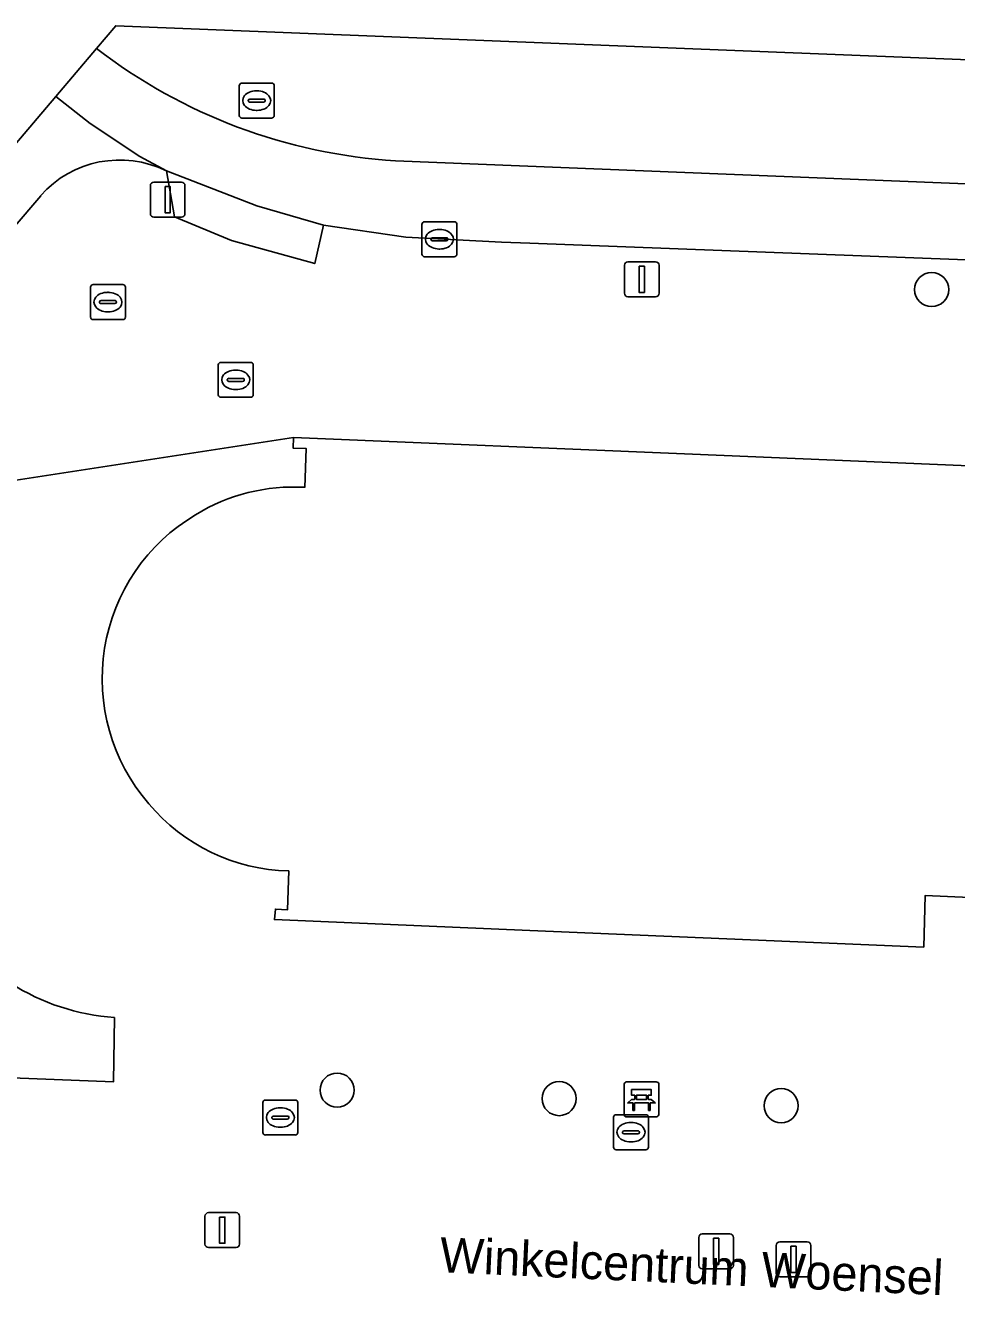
# Model space of a CAD drawing. Extents: x 160888 to 161385, y 386490 to 386908.
# Drawn here: x 160985.57 to 161012.2, y 386871.04 to 386907.8 of the extents above; entities that cross this region are included whole.
import ezdxf

# ---------------------------------------------------------------- set-up
doc = ezdxf.new("R2010")
doc.units = 0
for name, color, linetype in [('IMGEO_Bank', 7, 'Continuous'), ('IMGEO_Boom', 7, 'Continuous'), ('IMGEO_Brandkraan', 7, 'Continuous'), ('IMGEO_Fietspad_open', 7, 'Continuous'), ('IMGEO_Groenvoorziening', 7, 'Continuous'), ('IMGEO_Kolk', 7, 'Continuous'), ('IMGEO_Lichtmast', 7, 'Continuous'), ('IMGEO_Openbare_ruimte_label', 7, 'Continuous'), ('IMGEO_Pand', 7, 'Continuous'), ('IMGEO_Rijbaan_lokaal_gesloten', 7, 'Continuous'), ('IMGEO_Rioolput', 7, 'Continuous'), ('IMGEO_Voetpad_open', 7, 'Continuous')]:
    doc.layers.add(name, color=color, linetype=linetype)

msp = doc.modelspace()

# ---------------------------------------------------------------- linework, layer by layer
at = {"layer": 'IMGEO_Bank'}
for p, q in [((161002.695, 386876.655), (161002.695, 386877.496)), ((161002.695, 386877.496), (161002.695, 386876.655)), ((161002.77, 386877.58), (161003.611, 386877.58)), ((161003.611, 386877.58), (161002.77, 386877.58)), ((161003.695, 386877.505), (161003.695, 386876.664)), ((161003.695, 386876.664), (161003.695, 386877.505)), ((161003.004, 386877.086), (161003.004, 386877.192)), ((161003.048, 386877.192), (161003.048, 386877.086)), ((161003.336, 386877.198), (161003.054, 386877.198)), ((161003.054, 386877.08), (161003.336, 386877.08)), ((161003.342, 386877.086), (161003.342, 386877.192)), ((161003.386, 386877.192), (161003.386, 386877.086)), ((161003.392, 386876.978), (161002.999, 386876.978)), ((161003.62, 386876.58), (161002.779, 386876.58)), ((161002.779, 386876.58), (161003.62, 386876.58))]:
    msp.add_line(p, q, dxfattribs=at)
for points in [[(161002.942, 386876.978), (161002.8, 386876.978), (161002.912, 386877.08), (161002.998, 386877.08)], [(161002.998, 386877.198), (161002.912, 386877.198), (161002.912, 386877.359), (161003.475, 386877.359), (161003.475, 386877.198), (161003.392, 386877.198)], [(161003.392, 386877.08), (161003.475, 386877.08), (161003.587, 386876.978), (161003.448, 386876.978)], [(161002.992, 386876.971), (161002.992, 386876.764), (161002.949, 386876.764), (161002.949, 386876.971)], [(161003.442, 386876.971), (161003.442, 386876.764), (161003.398, 386876.764), (161003.398, 386876.971)]]:
    msp.add_lwpolyline(points, dxfattribs=at)
for centre, radius, start, end in [((161002.773, 386877.502), 0.0779, 92.4484, 184.2845), ((161002.773, 386877.502), 0.0779, 92.4484, 184.2845), ((161003.617, 386877.502), 0.0779, 2.4484, 94.2845), ((161003.617, 386877.502), 0.0779, 2.4484, 94.2845), ((161002.997, 386877.191), 0.00671, 2.8957, 87.1043), ((161002.997, 386877.087), 0.00671, 272.8957, 357.1043), ((161003.054, 386877.191), 0.00671, 92.8957, 177.1043), ((161003.054, 386877.087), 0.00671, 182.8957, 267.1043), ((161003.336, 386877.191), 0.00671, 2.8957, 87.1043), ((161003.336, 386877.087), 0.00671, 272.8957, 357.1043), ((161003.393, 386877.191), 0.00671, 92.8957, 177.1043), ((161003.393, 386877.087), 0.00671, 182.8957, 267.1043), ((161002.942, 386876.971), 0.00671, 2.8957, 87.1043), ((161002.999, 386876.971), 0.00671, 92.8957, 177.1043), ((161003.391, 386876.971), 0.00671, 2.8957, 87.1043), ((161003.448, 386876.971), 0.00671, 92.8957, 177.1043), ((161002.773, 386876.658), 0.0779, 182.4484, 274.2845), ((161002.773, 386876.658), 0.0779, 182.4484, 274.2845), ((161003.617, 386876.658), 0.0779, 272.4484, 4.2845), ((161003.617, 386876.658), 0.0779, 272.4484, 4.2845)]:
    msp.add_arc(centre, radius, start, end, dxfattribs=at)
at = {"layer": 'IMGEO_Boom'}
for centre in [(161011.496, 386900.25), (160994.484, 386877.344), (161000.837, 386877.102), (161007.19, 386876.899)]:
    msp.add_circle(centre, 0.489, dxfattribs=at)
at = {"layer": 'IMGEO_Brandkraan'}
for p, q in [((160987.426, 386899.465), (160987.426, 386900.317)), ((160987.501, 386900.391), (160988.353, 386900.391)), ((160988.427, 386900.317), (160988.427, 386899.465)), ((160987.685, 386899.885), (160987.685, 386899.897)), ((160987.728, 386899.934), (160988.126, 386899.934)), ((160987.914, 386900.171), (160987.939, 386900.171)), ((160988.169, 386899.897), (160988.169, 386899.885)), ((160988.123, 386899.848), (160987.725, 386899.848)), ((160987.937, 386899.611), (160987.912, 386899.611)), ((160988.353, 386899.391), (160987.501, 386899.391))]:
    msp.add_line(p, q, dxfattribs=at)
for points in [[(160987.426, 386899.465), (160987.426, 386900.317)], [(160987.501, 386900.391), (160988.353, 386900.391)], [(160988.427, 386900.317), (160988.427, 386899.465)], [(160988.353, 386899.391), (160987.501, 386899.391)]]:
    msp.add_lwpolyline(points, dxfattribs=at)
for centre, radius, start, end in [((160987.503, 386900.315), 0.0765, 91.552, 178.448), ((160987.503, 386900.315), 0.0765, 91.552, 178.448), ((160988.351, 386900.315), 0.0765, 1.552, 88.448), ((160988.351, 386900.315), 0.0765, 1.552, 88.448), ((160987.725, 386899.894), 0.0403, 85.8775, 175.7526), ((160987.722, 386899.884), 0.0366, 178.938, 274.7102), ((160988.126, 386899.891), 0.043, 264.8664, 352.4533), ((160988.13, 386899.896), 0.0386, 1.7309, 96.639), ((160987.503, 386899.467), 0.0765, 181.552, 268.448), ((160987.503, 386899.467), 0.0765, 181.552, 268.448), ((160988.351, 386899.467), 0.0765, 271.552, 358.448), ((160988.351, 386899.467), 0.0765, 271.552, 358.448)]:
    msp.add_arc(centre, radius, start, end, dxfattribs=at)
for centre, major_axis, ratio, start_param, end_param in [((160987.913, 386899.891), (-0.387, 0.002), 0.722429, 4.712389, 7.853982), ((160987.938, 386899.891), (-0.39, 0.002), 0.717154, 1.570796, 4.712389)]:
    msp.add_ellipse(centre, major_axis=major_axis, ratio=ratio, start_param=start_param, end_param=end_param, dxfattribs=at)
at = {"layer": 'IMGEO_Fietspad_open'}
for points in [[(160989.598, 386903.645), (160988.842, 386904.061), (160987.414, 386904.997), (160986.431, 386905.776), (160986.431, 386905.776), (160961.742, 386876.676), (160958.056, 386876.81)], [(160964.887, 386878.266), (160981.133, 386897.248), (160986.001, 386902.936)]]:
    msp.add_lwpolyline(points, dxfattribs=at)
msp.add_arc((160988.262, 386900.942), 3.015, 63.7043, 138.5969, dxfattribs=at)
at = {"layer": 'IMGEO_Groenvoorziening'}
msp.add_lwpolyline([(160984.295, 386894.643), (160982.853, 386895.847), (160973.768, 386885.289), (160973.52, 386878.149), (160988.085, 386877.583), (160988.113, 386879.42)], dxfattribs=at)
msp.add_arc((160988.551, 386885.739), 6.334, 237.4467, 266.031, dxfattribs=at)
at = {"layer": 'IMGEO_Kolk'}
for p, q in [((160996.911, 386901.264), (160996.911, 386902.116)), ((160996.986, 386902.19), (160997.838, 386902.19)), ((160997.912, 386902.116), (160997.912, 386901.264)), ((160997.17, 386901.684), (160997.17, 386901.696)), ((160997.213, 386901.733), (160997.611, 386901.733)), ((160997.399, 386901.97), (160997.424, 386901.97)), ((160997.654, 386901.696), (160997.654, 386901.684)), ((160997.608, 386901.647), (160997.21, 386901.647)), ((160997.422, 386901.41), (160997.397, 386901.41)), ((160997.838, 386901.19), (160996.986, 386901.19)), ((160992.359, 386876.134), (160992.359, 386876.986)), ((160992.434, 386877.06), (160993.286, 386877.06)), ((160992.847, 386876.84), (160992.872, 386876.84)), ((160993.36, 386876.986), (160993.36, 386876.134)), ((160992.618, 386876.554), (160992.618, 386876.566)), ((160993.056, 386876.517), (160992.658, 386876.517)), ((160992.661, 386876.603), (160993.059, 386876.603)), ((160993.102, 386876.566), (160993.102, 386876.554)), ((161002.393, 386875.714), (161002.393, 386876.566)), ((161002.468, 386876.64), (161003.32, 386876.64)), ((161002.881, 386876.42), (161002.906, 386876.42)), ((161003.394, 386876.566), (161003.394, 386875.714)), ((160993.286, 386876.06), (160992.434, 386876.06)), ((160992.87, 386876.28), (160992.845, 386876.28)), ((161002.652, 386876.134), (161002.652, 386876.146)), ((161003.09, 386876.097), (161002.692, 386876.097)), ((161002.695, 386876.183), (161003.093, 386876.183)), ((161003.136, 386876.146), (161003.136, 386876.134)), ((161003.32, 386875.64), (161002.468, 386875.64)), ((161002.904, 386875.86), (161002.879, 386875.86))]:
    msp.add_line(p, q, dxfattribs=at)
for points in [[(160996.911, 386901.264), (160996.911, 386902.116)], [(160996.986, 386902.19), (160997.838, 386902.19)], [(160997.912, 386902.116), (160997.912, 386901.264)], [(160997.838, 386901.19), (160996.986, 386901.19)], [(160992.359, 386876.134), (160992.359, 386876.986)], [(160992.434, 386877.06), (160993.286, 386877.06)], [(160993.36, 386876.986), (160993.36, 386876.134)], [(161002.393, 386875.714), (161002.393, 386876.566)], [(161002.468, 386876.64), (161003.32, 386876.64)], [(161003.394, 386876.566), (161003.394, 386875.714)], [(160993.286, 386876.06), (160992.434, 386876.06)], [(161003.32, 386875.64), (161002.468, 386875.64)]]:
    msp.add_lwpolyline(points, dxfattribs=at)
for centre, radius, start, end in [((160996.988, 386902.114), 0.0765, 91.552, 178.448), ((160996.988, 386902.114), 0.0765, 91.552, 178.448), ((160997.836, 386902.114), 0.0765, 1.552, 88.448), ((160997.836, 386902.114), 0.0765, 1.552, 88.448), ((160997.21, 386901.693), 0.0403, 85.8775, 175.7526), ((160997.615, 386901.695), 0.0386, 1.7309, 96.639), ((160997.207, 386901.683), 0.0366, 178.938, 274.7102), ((160997.611, 386901.69), 0.043, 264.8664, 352.4533), ((160996.988, 386901.266), 0.0765, 181.552, 268.448), ((160996.988, 386901.266), 0.0765, 181.552, 268.448), ((160997.836, 386901.266), 0.0765, 271.552, 358.448), ((160997.836, 386901.266), 0.0765, 271.552, 358.448), ((160992.436, 386876.984), 0.0765, 91.552, 178.448), ((160992.436, 386876.984), 0.0765, 91.552, 178.448), ((160993.284, 386876.984), 0.0765, 1.552, 88.448), ((160993.284, 386876.984), 0.0765, 1.552, 88.448), ((160992.658, 386876.563), 0.0403, 85.8775, 175.7526), ((160992.655, 386876.553), 0.0366, 178.938, 274.7102), ((160993.059, 386876.56), 0.043, 264.8664, 352.4533), ((160993.063, 386876.565), 0.0386, 1.7309, 96.639), ((161002.47, 386876.564), 0.0765, 91.552, 178.448), ((161002.47, 386876.564), 0.0765, 91.552, 178.448), ((161003.318, 386876.564), 0.0765, 1.552, 88.448), ((161003.318, 386876.564), 0.0765, 1.552, 88.448), ((160992.436, 386876.136), 0.0765, 181.552, 268.448), ((160992.436, 386876.136), 0.0765, 181.552, 268.448), ((160993.284, 386876.136), 0.0765, 271.552, 358.448), ((160993.284, 386876.136), 0.0765, 271.552, 358.448), ((161002.692, 386876.143), 0.0403, 85.8775, 175.7526), ((161002.689, 386876.133), 0.0366, 178.938, 274.7102), ((161003.093, 386876.14), 0.043, 264.8664, 352.4533), ((161003.097, 386876.145), 0.0386, 1.7309, 96.639), ((161002.47, 386875.716), 0.0765, 181.552, 268.448), ((161002.47, 386875.716), 0.0765, 181.552, 268.448), ((161003.318, 386875.716), 0.0765, 271.552, 358.448), ((161003.318, 386875.716), 0.0765, 271.552, 358.448)]:
    msp.add_arc(centre, radius, start, end, dxfattribs=at)
for centre, major_axis, ratio, start_param, end_param in [((160997.398, 386901.69), (-0.387, 0.002), 0.722429, 4.712389, 7.853982), ((160997.423, 386901.69), (-0.39, 0.002), 0.717154, 1.570796, 4.712389), ((160992.846, 386876.56), (-0.387, 0.002), 0.722429, 4.712389, 7.853982), ((160992.871, 386876.56), (-0.39, 0.002), 0.717154, 1.570796, 4.712389), ((161002.88, 386876.14), (-0.387, 0.002), 0.722429, 4.712389, 7.853982), ((161002.905, 386876.14), (-0.39, 0.002), 0.717154, 1.570796, 4.712389)]:
    msp.add_ellipse(centre, major_axis=major_axis, ratio=ratio, start_param=start_param, end_param=end_param, dxfattribs=at)
at = {"layer": 'IMGEO_Lichtmast'}
for p, q in [((160989.14, 386902.422), (160989.14, 386903.222)), ((160989.14, 386903.222), (160989.14, 386902.422)), ((160989.24, 386903.322), (160990.03, 386903.322)), ((160990.03, 386903.322), (160989.24, 386903.322)), ((160990.13, 386903.222), (160990.13, 386902.422)), ((160990.13, 386902.422), (160990.13, 386903.222)), ((160990.03, 386902.322), (160989.24, 386902.322)), ((160989.24, 386902.322), (160990.03, 386902.322)), ((161002.807, 386901.044), (161003.597, 386901.044)), ((161003.597, 386901.044), (161002.807, 386901.044)), ((161002.707, 386900.144), (161002.707, 386900.944)), ((161002.707, 386900.944), (161002.707, 386900.144)), ((161003.697, 386900.944), (161003.697, 386900.144)), ((161003.697, 386900.144), (161003.697, 386900.944)), ((161003.597, 386900.044), (161002.807, 386900.044)), ((161002.807, 386900.044), (161003.597, 386900.044)), ((160990.803, 386873.838), (160991.593, 386873.838)), ((160991.593, 386873.838), (160990.803, 386873.838)), ((160990.703, 386872.938), (160990.703, 386873.738)), ((160990.703, 386873.738), (160990.703, 386872.938)), ((160991.693, 386873.738), (160991.693, 386872.938)), ((160991.693, 386872.938), (160991.693, 386873.738)), ((161004.833, 386872.33), (161004.833, 386873.13)), ((161004.833, 386873.13), (161004.833, 386872.33)), ((161004.933, 386873.23), (161005.723, 386873.23)), ((161005.723, 386873.23), (161004.933, 386873.23)), ((161005.823, 386873.13), (161005.823, 386872.33)), ((161005.823, 386872.33), (161005.823, 386873.13)), ((160991.593, 386872.838), (160990.803, 386872.838)), ((160990.803, 386872.838), (160991.593, 386872.838)), ((161007.05, 386872.101), (161007.05, 386872.901)), ((161007.05, 386872.901), (161007.05, 386872.101)), ((161007.15, 386873.001), (161007.94, 386873.001)), ((161007.94, 386873.001), (161007.15, 386873.001)), ((161008.04, 386872.901), (161008.04, 386872.101)), ((161008.04, 386872.101), (161008.04, 386872.901)), ((161005.723, 386872.23), (161004.933, 386872.23)), ((161004.933, 386872.23), (161005.723, 386872.23)), ((161007.94, 386872.001), (161007.15, 386872.001)), ((161007.15, 386872.001), (161007.94, 386872.001))]:
    msp.add_line(p, q, dxfattribs=at)
for points in [[(160989.56, 386903.197), (160989.71, 386903.197), (160989.71, 386902.447), (160989.56, 386902.447), (160989.56, 386903.197)], [(161003.127, 386900.919), (161003.277, 386900.919), (161003.277, 386900.169), (161003.127, 386900.169), (161003.127, 386900.919)], [(160991.123, 386873.713), (160991.273, 386873.713), (160991.273, 386872.963), (160991.123, 386872.963), (160991.123, 386873.713)], [(161005.253, 386873.105), (161005.403, 386873.105), (161005.403, 386872.355), (161005.253, 386872.355), (161005.253, 386873.105)], [(161007.47, 386872.876), (161007.62, 386872.876), (161007.62, 386872.126), (161007.47, 386872.126), (161007.47, 386872.876)]]:
    msp.add_lwpolyline(points, dxfattribs=at)
for centre, start, end in [((160989.24, 386903.222), 90, 180), ((160989.24, 386903.222), 90, 180), ((160990.03, 386903.222), 0, 90), ((160990.03, 386903.222), 360, 90), ((160989.24, 386902.422), 180, 270), ((160989.24, 386902.422), 180, 270), ((160990.03, 386902.422), 270, 0), ((160990.03, 386902.422), 270, 0), ((161002.807, 386900.944), 90, 180), ((161002.807, 386900.944), 90, 180), ((161003.597, 386900.944), 0, 90), ((161003.597, 386900.944), 360, 90), ((161002.807, 386900.144), 180, 270), ((161002.807, 386900.144), 180, 270), ((161003.597, 386900.144), 270, 0), ((161003.597, 386900.144), 270, 0), ((160990.803, 386873.738), 90, 180), ((160990.803, 386873.738), 90, 180), ((160991.593, 386873.738), 0, 90), ((160991.593, 386873.738), 360, 90), ((161004.933, 386873.13), 90, 180), ((161004.933, 386873.13), 90, 180), ((161005.723, 386873.13), 0, 90), ((161005.723, 386873.13), 360, 90), ((160990.803, 386872.938), 180, 270), ((160990.803, 386872.938), 180, 270), ((160991.593, 386872.938), 270, 0), ((160991.593, 386872.938), 270, 0), ((161007.15, 386872.901), 90, 180), ((161007.15, 386872.901), 90, 180), ((161007.94, 386872.901), 0, 90), ((161007.94, 386872.901), 360, 90), ((161004.933, 386872.33), 180, 270), ((161004.933, 386872.33), 180, 270), ((161005.723, 386872.33), 270, 0), ((161005.723, 386872.33), 270, 0), ((161007.15, 386872.101), 180, 270), ((161007.15, 386872.101), 180, 270), ((161007.94, 386872.101), 270, 0), ((161007.94, 386872.101), 270, 0)]:
    msp.add_arc(centre, 0.1, start, end, dxfattribs=at)
at = {"layer": 'IMGEO_Pand'}
for points in [[(161029.981, 386894.476), (161004.65, 386895.537), (160993.236, 386896.016), (160993.223, 386895.716), (160993.603, 386895.7), (160993.557, 386894.591)], [(160993.1, 386883.616), (160993.063, 386882.501), (160992.717, 386882.523), (160992.691, 386882.225), (161000, 386881.915), (161011.271, 386881.437), (161011.314, 386882.915), (161012.587, 386882.859)]]:
    msp.add_lwpolyline(points, dxfattribs=at)
for centre, radius, start, end in [((160993.236, 386889.252), 5.349, 86.5601, 121.5901), ((160993.216, 386889.113), 5.457, 120.6453, 220.918), ((160993.225, 386889.015), 5.401, 220.0666, 268.6709)]:
    msp.add_arc(centre, radius, start, end, dxfattribs=at)
at = {"layer": 'IMGEO_Rijbaan_lokaal_gesloten'}
for points in [[(161112.38, 386902.848), (160988.148, 386907.8), (160987.595, 386907.148)], [(160987.595, 386907.148), (160986.431, 386905.776)], [(160986.431, 386905.776), (160986.431, 386905.776), (160987.414, 386904.997), (160988.842, 386904.061), (160989.598, 386903.645), (160992.187, 386902.648), (160994.092, 386902.091), (160996.449, 386901.746), (160999.189, 386901.61), (161000, 386901.579), (161012.233, 386901.108), (161035.324, 386900.473), (161035.479, 386900.468), (161040.028, 386900.281), (161040.12, 386902.25), (161064.059, 386901.284), (161073.486, 386900.908), (161109.397, 386899.476), (161112.234, 386899.353), (161112.299, 386900.982), (161040.205, 386903.901), (161035.665, 386902.345), (160996.157, 386903.935)], [(160996.157, 386903.935), (161035.665, 386902.345), (161040.205, 386903.901), (161112.299, 386900.982), (161112.38, 386902.848)]]:
    msp.add_lwpolyline(points, dxfattribs=at)
msp.add_arc((160997.116, 386919.506), 15.6, 232.3867, 266.4746, dxfattribs=at)
msp.add_arc((160997.116, 386919.506), 15.6, 232.3867, 266.4746, dxfattribs=at)
at = {"layer": 'IMGEO_Rioolput'}
for p, q in [((160991.758, 386906.157), (160992.61, 386906.157)), ((160991.683, 386905.231), (160991.683, 386906.083)), ((160992.171, 386905.937), (160992.196, 386905.937)), ((160992.684, 386906.083), (160992.684, 386905.231)), ((160991.942, 386905.651), (160991.942, 386905.663)), ((160992.38, 386905.614), (160991.982, 386905.614)), ((160991.985, 386905.7), (160992.383, 386905.7)), ((160992.194, 386905.377), (160992.169, 386905.377)), ((160992.426, 386905.663), (160992.426, 386905.651)), ((160992.61, 386905.157), (160991.758, 386905.157)), ((160991.083, 386897.241), (160991.083, 386898.093)), ((160991.158, 386898.167), (160992.01, 386898.167)), ((160992.084, 386898.093), (160992.084, 386897.241)), ((160991.342, 386897.661), (160991.342, 386897.673)), ((160991.385, 386897.71), (160991.783, 386897.71)), ((160991.571, 386897.947), (160991.596, 386897.947)), ((160991.826, 386897.673), (160991.826, 386897.661)), ((160991.78, 386897.624), (160991.382, 386897.624)), ((160991.594, 386897.387), (160991.569, 386897.387)), ((160992.01, 386897.167), (160991.158, 386897.167))]:
    msp.add_line(p, q, dxfattribs=at)
for points in [[(160991.758, 386906.157), (160992.61, 386906.157)], [(160991.683, 386905.231), (160991.683, 386906.083)], [(160992.684, 386906.083), (160992.684, 386905.231)], [(160992.61, 386905.157), (160991.758, 386905.157)], [(160991.083, 386897.241), (160991.083, 386898.093)], [(160991.158, 386898.167), (160992.01, 386898.167)], [(160992.084, 386898.093), (160992.084, 386897.241)], [(160992.01, 386897.167), (160991.158, 386897.167)]]:
    msp.add_lwpolyline(points, dxfattribs=at)
for centre, radius, start, end in [((160991.76, 386906.081), 0.0765, 91.552, 178.448), ((160991.76, 386906.081), 0.0765, 91.552, 178.448), ((160992.608, 386906.081), 0.0765, 1.552, 88.448), ((160992.608, 386906.081), 0.0765, 1.552, 88.448), ((160991.982, 386905.66), 0.0403, 85.8775, 175.7526), ((160991.979, 386905.65), 0.0366, 178.938, 274.7102), ((160992.383, 386905.657), 0.043, 264.8664, 352.4533), ((160992.387, 386905.662), 0.0386, 1.7309, 96.639), ((160991.76, 386905.233), 0.0765, 181.552, 268.448), ((160991.76, 386905.233), 0.0765, 181.552, 268.448), ((160992.608, 386905.233), 0.0765, 271.552, 358.448), ((160992.608, 386905.233), 0.0765, 271.552, 358.448), ((160991.16, 386898.091), 0.0765, 91.552, 178.448), ((160991.16, 386898.091), 0.0765, 91.552, 178.448), ((160992.008, 386898.091), 0.0765, 1.552, 88.448), ((160992.008, 386898.091), 0.0765, 1.552, 88.448), ((160991.382, 386897.67), 0.0403, 85.8775, 175.7526), ((160991.379, 386897.66), 0.0366, 178.938, 274.7102), ((160991.783, 386897.667), 0.043, 264.8664, 352.4533), ((160991.787, 386897.672), 0.0386, 1.7309, 96.639), ((160991.16, 386897.243), 0.0765, 181.552, 268.448), ((160991.16, 386897.243), 0.0765, 181.552, 268.448), ((160992.008, 386897.243), 0.0765, 271.552, 358.448), ((160992.008, 386897.243), 0.0765, 271.552, 358.448)]:
    msp.add_arc(centre, radius, start, end, dxfattribs=at)
for centre, major_axis, ratio, start_param, end_param in [((160992.17, 386905.657), (-0.387, 0.002), 0.722429, 4.712389, 7.853982), ((160992.195, 386905.657), (-0.39, 0.002), 0.717154, 1.570796, 4.712389), ((160991.57, 386897.667), (-0.387, 0.002), 0.722429, 4.712389, 7.853982), ((160991.595, 386897.667), (-0.39, 0.002), 0.717154, 1.570796, 4.712389)]:
    msp.add_ellipse(centre, major_axis=major_axis, ratio=ratio, start_param=start_param, end_param=end_param, dxfattribs=at)
at = {"layer": 'IMGEO_Voetpad_open'}
msp.add_lwpolyline([(160989.828, 386902.333), (160991.464, 386901.654), (160993.843, 386900.994), (160994.092, 386902.091), (160992.187, 386902.648), (160989.598, 386903.645)], close=True, dxfattribs=at)
for points in [[(161012.233, 386901.108), (161000, 386901.579), (160999.189, 386901.61), (160996.449, 386901.746), (160994.092, 386902.091), (160993.843, 386900.994), (160991.464, 386901.654), (160989.828, 386902.333), (160989.598, 386903.645)], [(160986.001, 386902.936), (160981.133, 386897.248), (160982.853, 386895.847), (160984.295, 386894.643), (160993.236, 386896.016), (161004.65, 386895.537), (161029.981, 386894.476), (161035.955, 386894.217), (161041.701, 386893.968), (161046.043, 386894.008), (161046.299, 386893.997), (161046.293, 386893.867), (161055.667, 386893.489), (161080.645, 386892.481), (161097.194, 386891.813), (161113.143, 386891.17), (161127.058, 386890.969), (161178.427, 386888.94)], [(160993.557, 386894.591), (160993.603, 386895.7), (160993.223, 386895.716), (160993.236, 386896.016), (160984.295, 386894.643)], [(160988.113, 386879.42), (160988.085, 386877.583), (160973.52, 386878.149), (160973.222, 386870.514), (160982.977, 386870.114), (160983.988, 386870.07), (160998.471, 386869.439), (161000, 386869.372), (161002.18, 386869.277), (161017.574, 386868.605), (161022.345, 386868.321), (161040.517, 386867.696), (161042.835, 386870.038), (161086.005, 386868.407), (161091.101, 386868.215), (161100.979, 386872.509), (161105.986, 386872.318), (161110.434, 386872.136), (161115.457, 386871.94), (161115.257, 386866.814), (161118.549, 386857.687), (161119.79, 386888.855)], [(161012.587, 386882.859), (161011.314, 386882.915), (161011.271, 386881.437), (161000, 386881.915), (160992.691, 386882.225), (160992.717, 386882.523), (160993.063, 386882.501), (160993.1, 386883.616)]]:
    msp.add_lwpolyline(points, dxfattribs=at)
for centre, radius, start, end in [((160988.262, 386900.942), 3.015, 63.7043, 138.5969), ((160993.236, 386889.252), 5.349, 86.5601, 121.5901), ((160993.216, 386889.113), 5.457, 120.6453, 220.918), ((160993.225, 386889.015), 5.401, 220.0666, 268.6709), ((160988.551, 386885.739), 6.334, 237.4467, 266.031)]:
    msp.add_arc(centre, radius, start, end, dxfattribs=at)

# ---------------------------------------------------------------- texts
at = {"layer": 'IMGEO_Openbare_ruimte_label'}
msp.add_text('Winkelcentrum Woensel', height=1, rotation=357.3636, dxfattribs=at).set_placement((160997.403, 386872.138))

doc.saveas('drawing.dxf')
